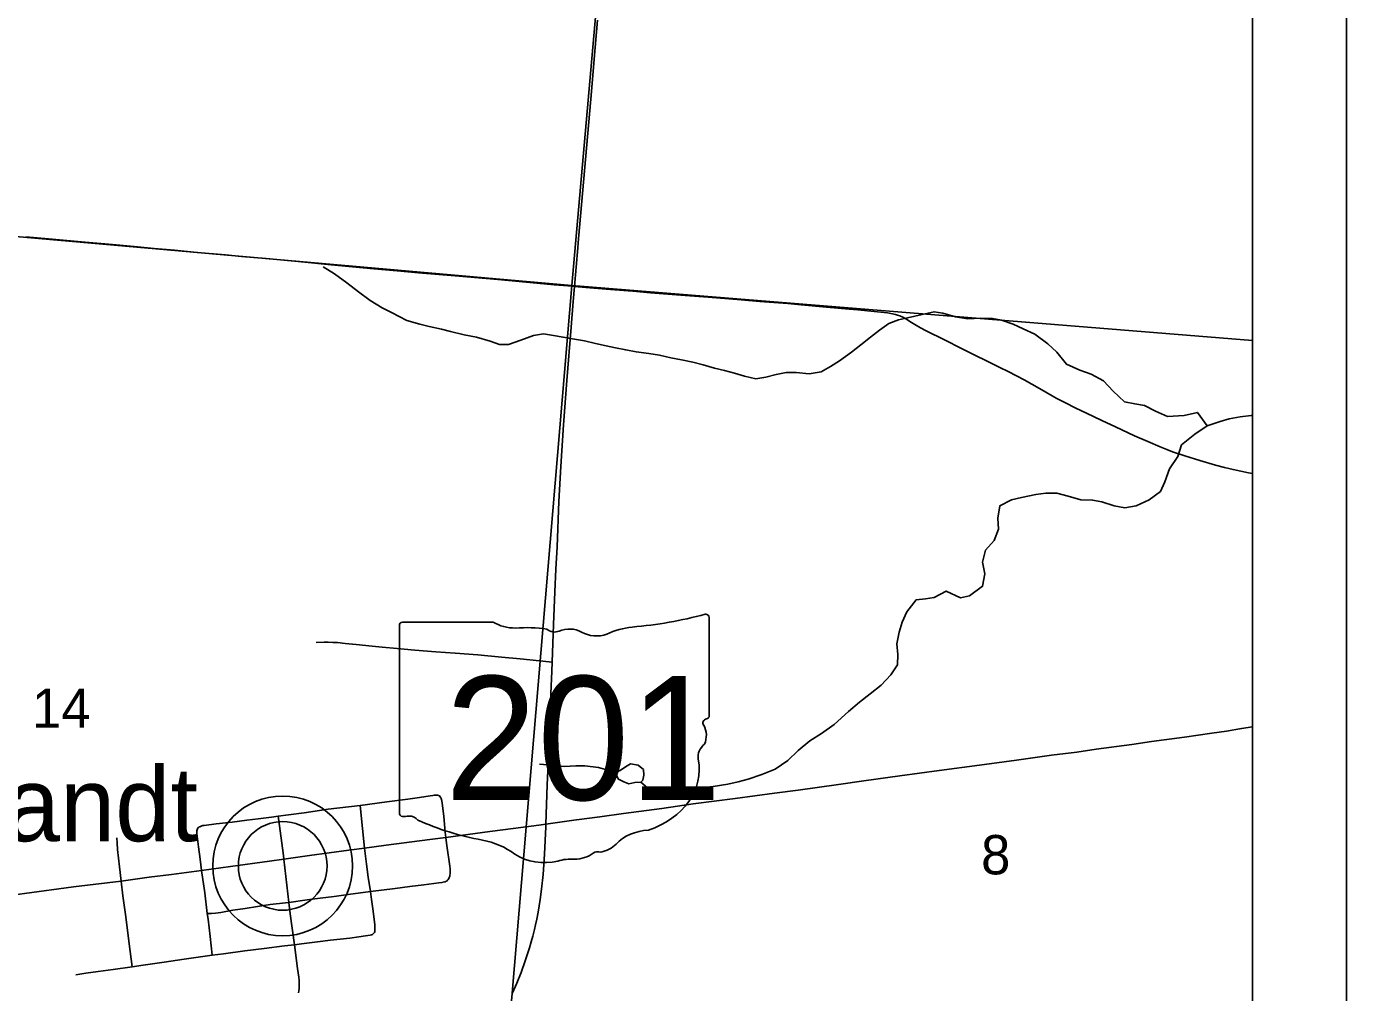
# Model space of a CAD drawing. Extents: x -38.1 to 35.9, y -2.7 to 28.5.
# Drawn here: x 13.609 to 15.015, y 16.204 to 17.233 of the extents above; entities that cross this region are included whole.
import ezdxf

# ---------------------------------------------------------------- set-up
doc = ezdxf.new("R2010")
doc.units = 0
for name, color, linetype in [('GM_X_City_Street_Text', 7, 'Continuous'), ('GM_X_County_Road_Text', 7, 'Continuous'), ('GM_X_County_ROW', 7, 'Continuous'), ('GM_X_Interchange_Ramps', 7, 'Continuous'), ('GM_X_Major_River', 7, 'Continuous'), ('GM_X_Major_River_Text', 7, 'Continuous'), ('GM_X_Minor_River', 7, 'Continuous'), ('GM_X_Section', 7, 'Continuous'), ('GM_X_Section_Text', 7, 'Continuous'), ('GM_X_State_Location', 7, 'Continuous'), ('GM_X_Township_Subdivision_Text', 7, 'Continuous'), ('GM_X_US_Route', 7, 'Continuous'), ('SC_Scratch10', 7, 'Continuous'), ('SH_Border', 7, 'Continuous'), ('SH_Data', 7, 'Continuous')]:
    doc.layers.add(name, color=color, linetype=linetype)

msp = doc.modelspace()

# ---------------------------------------------------------------- linework, layer by layer
at = {"layer": 'GM_X_City_Street_Text'}
for points in [[(13.6086, 17.0086), (13.6326, 17.0064), (13.6715, 17.003), (13.7007, 17.0003), (13.7239, 16.9982), (13.7452, 16.9963), (13.7668, 16.9943), (13.7909, 16.992), (13.8212, 16.9893), (13.8379, 16.9878), (13.8645, 16.9856), (13.8985, 16.9822), (13.9337, 16.9786), (13.9561, 16.9765), (13.979, 16.9744), (14.0038, 16.9723), (14.0265, 16.9704), (14.0655, 16.967), (14.111, 16.963), (14.1412, 16.9602), (14.1711, 16.9575), (14.1905, 16.9559), (14.1927, 16.9557)], [(14.1927, 16.9557), (14.2047, 16.9546), (14.2264, 16.9529), (14.2499, 16.9511), (14.2548, 16.9507)], [(14.2548, 16.9507), (14.2735, 16.9491), (14.3106, 16.9461), (14.3348, 16.9442), (14.37, 16.9414), (14.3898, 16.9398), (14.4196, 16.9375), (14.4338, 16.9361), (14.461, 16.9338), (14.4851, 16.9316), (14.4944, 16.9307), (14.5117, 16.9292), (14.5222, 16.9281), (14.5258, 16.9276), (14.5295, 16.9269), (14.5342, 16.9258), (14.5365, 16.9252), (14.5389, 16.9243), (14.5421, 16.9231), (14.545, 16.9215), (14.5498, 16.9185), (14.5551, 16.9152), (14.5611, 16.9116), (14.5669, 16.9086), (14.5864, 16.8987), (14.6047, 16.8895), (14.6454, 16.8695), (14.6544, 16.8651), (14.6631, 16.8606), (14.6713, 16.8562), (14.6794, 16.8517), (14.6902, 16.8455), (14.7053, 16.8369), (14.7147, 16.832), (14.7262, 16.8262), (14.7377, 16.8209), (14.7539, 16.8131), (14.7685, 16.8062), (14.7887, 16.7967), (14.8029, 16.7904), (14.816, 16.7848), (14.8232, 16.782), (14.8294, 16.7797), (14.8424, 16.7753), (14.8584, 16.7702), (14.875, 16.7654), (14.8846, 16.7628), (14.8937, 16.7606), (14.9102, 16.7573), (14.9146, 16.7564)]]:
    msp.add_lwpolyline(points, dxfattribs=at)
at = {"layer": 'GM_X_County_ROW'}
msp.add_line((13.8819, 16.3385), (13.8819, 16.3385), dxfattribs=at)
at = {"layer": 'GM_X_Interchange_Ramps'}
for points in [[(14.1621, 16.3829), (14.1636, 16.4249), (14.1652, 16.4622), (14.1661, 16.4901), (14.1684, 16.546), (14.1688, 16.5557), (14.1701, 16.5957), (14.1716, 16.6304), (14.1729, 16.6546), (14.174, 16.6782), (14.1761, 16.7266), (14.1781, 16.7638), (14.1809, 16.8085), (14.1845, 16.8556), (14.189, 16.9125), (14.1913, 16.9398), (14.1927, 16.9557), (14.1963, 16.9967), (14.1968, 17.0067), (14.1972, 17.0104), (14.2107, 17.1632), (14.2136, 17.1979), (14.2171, 17.2394)], [(14.1266, 16.2033), (14.1312, 16.2135), (14.1358, 16.2251), (14.1402, 16.2374), (14.1446, 16.2511), (14.1464, 16.2576), (14.1481, 16.2637), (14.1499, 16.2708), (14.1511, 16.2758), (14.1524, 16.2819), (14.1539, 16.2892), (14.1551, 16.296), (14.1562, 16.3027), (14.1576, 16.3138), (14.1591, 16.3293), (14.1606, 16.351), (14.162, 16.3802), (14.1621, 16.3829)]]:
    msp.add_lwpolyline(points, dxfattribs=at)
at = {"layer": 'GM_X_Major_River'}
for points in [[(14.1949, 16.3875), (14.2196, 16.3908), (14.2448, 16.3942), (14.2857, 16.3997), (14.3191, 16.4045), (14.3635, 16.4104), (14.4054, 16.4159), (14.4306, 16.4192), (14.4737, 16.4253), (14.5008, 16.429), (14.5389, 16.4343), (14.5807, 16.44), (14.6238, 16.4458), (14.6631, 16.4512), (14.7005, 16.4563), (14.7276, 16.4598), (14.7479, 16.4627), (14.786, 16.468), (14.807, 16.4709), (14.8421, 16.4756), (14.871, 16.4798), (14.8869, 16.4821), (14.9028, 16.4847), (14.9146, 16.4867)], [(13.5909, 16.3069), (13.6069, 16.3091), (13.6591, 16.3161), (13.7098, 16.3224), (13.7399, 16.3264), (13.7637, 16.3295), (13.7956, 16.3337), (13.8263, 16.3378), (13.868, 16.3435), (13.8832, 16.3456), (13.9104, 16.3495), (13.9523, 16.3552), (13.9691, 16.3575), (13.9921, 16.3605), (14.0387, 16.3668), (14.0556, 16.3689), (14.0791, 16.372), (14.1023, 16.375), (14.1274, 16.3783), (14.1545, 16.3818), (14.1621, 16.3829)], [(14.1621, 16.3829), (14.1719, 16.3843), (14.1919, 16.3871), (14.1949, 16.3875)]]:
    msp.add_lwpolyline(points, dxfattribs=at)
at = {"layer": 'GM_X_Major_River_Text'}
msp.add_line((13.8886, 16.2997), (13.8832, 16.3456), dxfattribs=at)
for points in [[(13.9175, 16.5764), (13.926, 16.5767), (13.9302, 16.5768), (13.9352, 16.5766), (13.9401, 16.5763), (13.9483, 16.5755), (13.96, 16.5744), (13.9773, 16.5727), (13.9878, 16.5716), (14.0037, 16.5701), (14.0225, 16.5684), (14.045, 16.5667), (14.0656, 16.5652), (14.0896, 16.5632), (14.115, 16.5609), (14.1348, 16.559), (14.1658, 16.556), (14.1688, 16.5557)], [(13.9644, 16.403), (13.9927, 16.4069), (14.015, 16.4097), (14.0275, 16.4115), (14.0389, 16.4132), (14.0417, 16.4135), (14.0431, 16.4137), (14.0443, 16.4137), (14.0456, 16.4137), (14.0468, 16.4137), (14.0478, 16.4134), (14.0487, 16.413)], [(14.0556, 16.3689), (14.0549, 16.3743), (14.0534, 16.391), (14.0518, 16.4056), (14.0515, 16.4076), (14.051, 16.4094), (14.0508, 16.4103), (14.0503, 16.4111), (14.0497, 16.4121), (14.0487, 16.413)], [(13.7924, 16.3795), (13.793, 16.38), (13.7936, 16.3803), (13.7943, 16.3806), (13.7951, 16.3809), (13.796, 16.3812), (13.797, 16.3814), (13.7983, 16.3816), (13.811, 16.3833), (13.8283, 16.3852), (13.8439, 16.3872), (13.8557, 16.3888), (13.8699, 16.3905), (13.8772, 16.3915)], [(13.8772, 16.3915), (13.8882, 16.393), (13.9047, 16.3952), (13.9305, 16.3988), (13.9644, 16.403)], [(13.8832, 16.3456), (13.8827, 16.3496), (13.8776, 16.389), (13.8772, 16.3915)], [(13.9691, 16.3575), (13.9669, 16.3782), (13.9644, 16.403)], [(13.7956, 16.3337), (13.794, 16.3458), (13.7923, 16.3587), (13.7906, 16.3729), (13.7905, 16.3746), (13.7905, 16.376), (13.7907, 16.377), (13.7911, 16.378), (13.7917, 16.3789), (13.7924, 16.3795)], [(13.7098, 16.3224), (13.7082, 16.3374), (13.7062, 16.3559), (13.7058, 16.3628), (13.7055, 16.3685)], [(14.0569, 16.3227), (14.0575, 16.3234), (14.0581, 16.3242), (14.0588, 16.3252), (14.0593, 16.3263), (14.0597, 16.3276), (14.0599, 16.3288), (14.0601, 16.33), (14.0602, 16.3315), (14.0603, 16.3331), (14.0602, 16.3354), (14.0599, 16.3384), (14.0592, 16.3431), (14.0574, 16.3553), (14.0563, 16.3628), (14.0556, 16.3689)], [(13.9753, 16.3113), (13.9731, 16.3265), (13.9712, 16.3405), (13.9691, 16.3575)], [(13.8016, 16.2877), (13.7989, 16.3098), (13.7956, 16.3337)], [(13.7216, 16.2311), (13.7185, 16.2555), (13.7176, 16.2616), (13.7144, 16.2869), (13.7117, 16.3066), (13.7098, 16.3224)], [(13.9753, 16.3113), (14.0017, 16.3145), (14.0173, 16.3165), (14.0323, 16.3184), (14.0481, 16.3204), (14.0514, 16.3208), (14.0528, 16.3211), (14.0543, 16.3214), (14.0552, 16.3217), (14.0561, 16.3221), (14.0569, 16.3227)], [(13.8886, 16.2997), (13.9081, 16.3023), (13.9218, 16.3041), (13.9368, 16.306), (13.9518, 16.3081), (13.9753, 16.3113)], [(13.9791, 16.2669), (13.9796, 16.2677), (13.9799, 16.2686), (13.9801, 16.2697), (13.9802, 16.2708), (13.9802, 16.2718), (13.9802, 16.2728), (13.98, 16.2758), (13.9782, 16.2904), (13.9765, 16.3027), (13.9753, 16.3113)], [(13.8016, 16.2877), (13.806, 16.2879), (13.8104, 16.2882), (13.816, 16.2889), (13.8287, 16.2912), (13.8421, 16.2933), (13.8551, 16.2953), (13.8686, 16.2973), (13.8849, 16.2992), (13.8886, 16.2997)], [(13.8944, 16.2546), (13.89, 16.2876), (13.8886, 16.2997)], [(13.8069, 16.2433), (13.8046, 16.2632), (13.8024, 16.2817), (13.8016, 16.2877)], [(13.8944, 16.2546), (13.9021, 16.2555), (13.9191, 16.2577), (13.9328, 16.2593), (13.9534, 16.2616), (13.963, 16.2628), (13.9701, 16.2639), (13.975, 16.2647), (13.9764, 16.2652), (13.9775, 16.2656), (13.9784, 16.2661), (13.9791, 16.2669)], [(13.8069, 16.2433), (13.8188, 16.245), (13.8416, 16.248), (13.8623, 16.2506), (13.884, 16.2533), (13.8944, 16.2546)], [(13.8987, 16.2032), (13.8992, 16.2054), (13.8995, 16.208), (13.8996, 16.2097), (13.8996, 16.211), (13.8996, 16.2126), (13.8995, 16.2147), (13.8993, 16.2166), (13.899, 16.2199), (13.8978, 16.2291), (13.8944, 16.2546)], [(13.7216, 16.2311), (13.7334, 16.2327), (13.7558, 16.236), (13.777, 16.2392), (13.8069, 16.2433)], [(13.6616, 16.2226), (13.6723, 16.2242), (13.6855, 16.2262), (13.7015, 16.2283), (13.7216, 16.2311)]]:
    msp.add_lwpolyline(points, dxfattribs=at)
at = {"layer": 'GM_X_Section'}
for points in [[(14.8661, 16.8072), (14.8558, 16.8215), (14.8416, 16.8184), (14.8241, 16.8173), (14.8113, 16.823), (14.7993, 16.829), (14.7891, 16.8308), (14.7781, 16.8329), (14.7662, 16.8442), (14.7558, 16.8551), (14.7427, 16.8623), (14.7306, 16.8664), (14.7163, 16.8728), (14.7063, 16.8856), (14.6967, 16.8946), (14.6828, 16.9048), (14.6704, 16.9105), (14.6595, 16.9157), (14.6474, 16.9198), (14.6376, 16.9215), (14.625, 16.9218), (14.6113, 16.9214), (14.5984, 16.9233), (14.5848, 16.9274), (14.5754, 16.9288), (14.5627, 16.926), (14.547, 16.9223), (14.5375, 16.9202), (14.5271, 16.9163), (14.5174, 16.9093), (14.5077, 16.9016), (14.4976, 16.8934), (14.4875, 16.8857), (14.4747, 16.8765), (14.465, 16.8703), (14.4554, 16.8648), (14.4424, 16.8625), (14.4287, 16.864), (14.4181, 16.8639), (14.4074, 16.8618), (14.3963, 16.8591), (14.3856, 16.8574), (14.3735, 16.86), (14.3629, 16.8633), (14.3523, 16.8662), (14.3417, 16.8688), (14.3296, 16.8721), (14.3186, 16.875), (14.3065, 16.8776), (14.2952, 16.8798), (14.2831, 16.8824), (14.2717, 16.8842), (14.2584, 16.886), (14.2471, 16.8882), (14.2364, 16.8904), (14.2262, 16.8925), (14.2149, 16.8951), (14.2031, 16.8977), (14.1906, 16.8999), (14.1804, 16.9016), (14.1702, 16.9034), (14.1596, 16.9052), (14.1489, 16.9035), (14.1354, 16.8986), (14.1224, 16.8939), (14.1129, 16.8938), (14.1027, 16.8975), (14.0883, 16.9016), (14.0751, 16.9042), (14.0607, 16.9076), (14.0509, 16.9101), (14.038, 16.9131), (14.0278, 16.9156), (14.0142, 16.9194), (13.9976, 16.9278), (13.9879, 16.933), (13.9751, 16.9409), (13.9628, 16.9499), (13.9501, 16.9597), (13.937, 16.9692), (13.925, 16.9767)], [(14.9146, 16.8184), (14.9132, 16.8182), (14.9014, 16.8169), (14.8895, 16.8146), (14.8799, 16.8118), (14.8661, 16.8072), (14.8529, 16.7984), (14.8389, 16.7869), (14.8348, 16.7745), (14.8261, 16.7614), (14.8212, 16.7475), (14.8164, 16.7373), (14.8044, 16.7285), (14.7905, 16.722), (14.7787, 16.72), (14.7673, 16.7222), (14.7541, 16.7263), (14.7442, 16.7281), (14.7317, 16.7284), (14.7181, 16.7325), (14.706, 16.7355), (14.6946, 16.7354), (14.6839, 16.7342), (14.6686, 16.7311), (14.6579, 16.7283), (14.6455, 16.7222), (14.6433, 16.7089), (14.6441, 16.6971), (14.6393, 16.6851), (14.6303, 16.675), (14.6269, 16.6622), (14.6296, 16.6496), (14.627, 16.6364), (14.6131, 16.6261), (14.6035, 16.624), (14.5884, 16.6312), (14.5757, 16.6243), (14.5662, 16.623), (14.5562, 16.6218), (14.5464, 16.6091), (14.5416, 16.5982), (14.5383, 16.5876), (14.5357, 16.5751), (14.5369, 16.5637), (14.5366, 16.5527), (14.5295, 16.5419), (14.519, 16.5311), (14.5073, 16.5219), (14.4961, 16.513), (14.4844, 16.5031), (14.4692, 16.489), (14.4556, 16.4795), (14.4433, 16.4718), (14.4308, 16.4614), (14.4199, 16.4507), (14.4064, 16.4415), (14.3921, 16.4358), (14.3776, 16.4308), (14.3668, 16.4281), (14.3557, 16.4257), (14.3401, 16.423), (14.3271, 16.4218), (14.3164, 16.4202), (14.3057, 16.4193)], [(14.2361, 16.437), (14.2305, 16.4398), (14.218, 16.4435), (14.2036, 16.445), (14.1941, 16.4452), (14.1819, 16.4444), (14.1682, 16.4459), (14.1553, 16.4469)], [(14.2749, 16.4178), (14.2633, 16.4276)], [(14.3057, 16.4193), (14.2954, 16.4176), (14.2844, 16.4168), (14.2749, 16.4178)]]:
    msp.add_lwpolyline(points, dxfattribs=at)
at = {"layer": 'GM_X_Section_Text'}
for p, q in [((14.3359, 16.4985), (14.3359, 16.6032)), ((14.0063, 16.5948), (14.0063, 16.3947)), ((14.1061, 16.5982), (14.0095, 16.5982)), ((14.3359, 16.4985), (14.3359, 16.4985))]:
    msp.add_line(p, q, dxfattribs=at)
for centre, major_axis, start_param, end_param in [((14.2185, 16.8711), (0.3495, 0), 4.814394, 5.042369), ((14.3322, 16.6036), (0.00367, 0), 6.141152, 7.989035), ((14.0101, 16.5952), (0.00382, 0), 1.712693, 3.28349), ((14.1291, 16.6215), (0.037, 0), 4.042523, 4.731795), ((14.1413, 16.4859), (0.133, 0), 1.404758, 1.657858), ((14.1715, 16.5962), (0.0107, 0), 3.836095, 5.185415), ((14.1872, 16.5731), (0.0222, 0), 0.950623, 2.079405), ((14.2159, 16.6048), (0.0267, 0), 4.081561, 5.145723), ((14.2631, 16.5371), (0.0703, 0), 1.699011, 2.107814), ((14.335, 16.4908), (0.00568, 0), 1.883978, 3.671073), ((14.2989, 16.4776), (0.0341, 0), 5.934695, 6.695948), ((14.332, 16.4981), (0.00393, 0), 5.05454, 6.418171), ((14.349, 16.4547), (0.0248, 0), 2.387724, 3.262537), ((14.2381, 16.4414), (0.0874, 0), 5.101752, 6.440018), ((14.0101, 16.3942), (0.00385, 0), 3.00124, 4.508301), ((14.0107, 16.4147), (0.0294, 0), 4.665946, 4.897461), ((14.0167, 16.3831), (0.0106, 0), 0.519207, 1.627899), ((14.1505, 16.5629), (0.2524, 0), 4.195997, 4.488961), ((14.2749, 16.3385), (0.0479, 0), 1.647645, 2.488434), ((14.0753, 16.3048), (0.079, 0), 0.823519, 1.323587), ((14.2143, 16.3753), (0.0282, 0), 4.937069, 5.64225), ((14.1607, 16.3821), (0.0501, 0), 4.026481, 4.996735), ((14.1933, 16.3671), (0.0267, 0), 4.691044, 5.507374), ((14.2175, 16.3477), (0.00752, 0), 1.147584, 2.315152), ((14.1897, 16.3129), (0.0412, 0), 1.495662, 1.94098)]:
    msp.add_ellipse(centre, major_axis=major_axis, ratio=0.8, start_param=start_param, end_param=end_param, dxfattribs=at)
at = {"layer": 'GM_X_State_Location'}
for radius in [0.0744, 0.0472]:
    msp.add_circle((13.8819, 16.3385), radius, dxfattribs=at)
at = {"layer": 'GM_X_US_Route'}
for points in [[(13.5108, 14.9991), (14.9146, 14.8694), (14.9146, 19.7308), (8.1146, 19.7308)], [(13.5108, 14.9991), (14.9146, 14.8694), (14.9146, 19.7308), (11.2375, 19.7308)]]:
    msp.add_lwpolyline(points, dxfattribs=at)
for points in [[(13.2752, 18.0746), (14.2779, 17.9561), (14.1898, 16.9568), (13.1908, 17.0449)], [(14.9146, 16.898), (14.9146, 17.9029), (14.2779, 17.9561), (14.1898, 16.9568)], [(13.1908, 17.0449), (14.1898, 16.9568), (14.1055, 15.9588), (13.1005, 16.0538)], [(14.9146, 15.8807), (14.9146, 16.898), (14.1898, 16.9568), (14.1055, 15.9588)]]:
    msp.add_lwpolyline(points, close=True, dxfattribs=at)
at = {"layer": 'SC_Scratch10'}
for points in [[(14.2653, 16.4298), (14.2665, 16.4351), (14.2659, 16.4412), (14.2603, 16.4459), (14.2524, 16.4472), (14.247, 16.4439), (14.2412, 16.4403), (14.2377, 16.4388), (14.2361, 16.437), (14.2394, 16.4308), (14.2451, 16.428)], [(14.2451, 16.428), (14.2503, 16.426), (14.2568, 16.4273), (14.2633, 16.4276), (14.2653, 16.4298)]]:
    msp.add_lwpolyline(points, dxfattribs=at)
at = {"layer": 'SH_Border'}
msp.add_line((14.9146, 19.7308), (14.9146, 12.9308), dxfattribs=at)
at = {"layer": 'SH_Data'}
msp.add_line((15.0146, 19.8308), (15.0146, 12.8308), dxfattribs=at)

# ---------------------------------------------------------------- texts
at = {"layer": 'GM_X_County_Road_Text'}
for s in ['s', 'r']:
    msp.add_text(s, height=0.000189, dxfattribs=at).set_placement((14.1674, 16.4814))
msp.add_text('201', height=0.000189, rotation=0, dxfattribs=at).set_placement((14.1005, 16.4676))
at = {"layer": 'GM_X_Minor_River'}
for s, height, p in [('14', 0.04186, (13.6151, 16.4856)), ('8', 0.0419, (14.6255, 16.3295))]:
    msp.add_text(s, height=height, rotation=0, dxfattribs=at).set_placement(p)
at = {"layer": 'GM_X_Section_Text'}
msp.add_text('201', height=0.13184, dxfattribs=at).set_placement((14.0549, 16.4088))
at = {"layer": 'GM_X_Township_Subdivision_Text'}
msp.add_text('Brandt', height=0.07898, rotation=0, dxfattribs=at).set_placement((13.4805, 16.3648))

doc.saveas('drawing.dxf')
